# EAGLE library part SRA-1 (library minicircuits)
Frequency Mixer Level 7 (LO Power + 7 dBm) Source: minicircuits.com .. SRA-1+.pdf
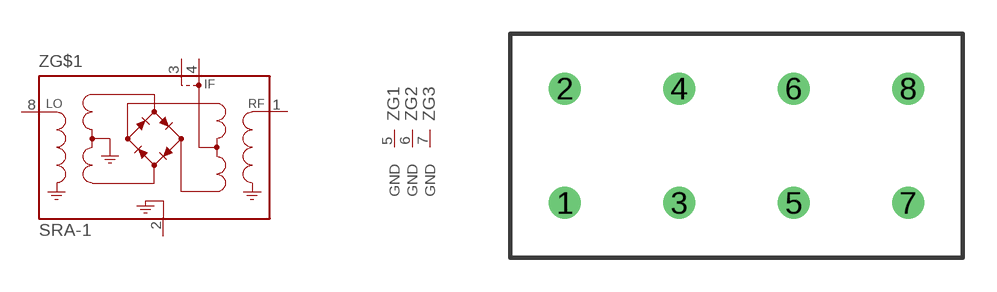
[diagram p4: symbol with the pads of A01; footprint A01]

Designator prefix Z; gates G$1=MIXER G1=GROUND G2=GROUND G3=GROUND

## SRA-1 (OC_FARNELL: unknown; OC_NEWARK: unknown)  [A01]
1  G$1:R  pas
2  G$1:CASEGROUND  pas
3  G$1:IF  pas
4  G$1:IF  pas
5  G1:GND  pwr
6  G2:GND  pwr
7  G3:GND  pwr
8  G$1:L  pas

## Footprint A01 (pad centres in mm)
CASE STYLE A01 Source: minicircuits.com .. PBP-10.7+.pdf
drill 0.9 pad 1.422 round: 1 -7.62,-2.54; 2 -7.62,2.54; 3 -2.54,-2.54; 4 -2.54,2.54; 5 2.54,-2.54; 6 2.54,2.54; 7 7.62,-2.54; 8 7.62,2.54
